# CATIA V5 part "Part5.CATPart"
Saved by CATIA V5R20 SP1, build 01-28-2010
Part number: Part3
Material "Iron": density 7870 kg/m3, Young's modulus 1.2e+11 Pa, Poisson ratio 0.291, thermal expansion 1.21e-05 1/K
Bounding box of the stored display mesh (mm): x -33.596 to 19.999, y -10 to 10, z -170 to 85.757
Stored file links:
  E:\Ehsan\My Websites\CATIA98.ir\3. Tutorials\3. Assembely Design\Assembly Design-17\Part5.CATPart
  D:\CATIA V5R20\B20\intel_a\startup\materials\Catalog.CATMaterial
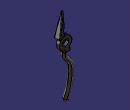
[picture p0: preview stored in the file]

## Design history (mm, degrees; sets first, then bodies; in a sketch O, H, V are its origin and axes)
Body1 (main body), material "Iron"
  Sketch1 on zx-plane, origin (0, 0, 0), H (-1, 0, 0), V (0, 0, 1)
    arc A1 centre (0, 0) radius 20 from (0, 20) to (-14.8215, 13.4284) ccw
    circle A2 centre (0, 0) radius 10
    line L1 (0, 20) -> (0, 89.7223)
    line L2 (-17.7324, 14.0566) -> (-14.8215, 13.4284)
    line L3 (0, 89.7223) -> (-1.4049, 89.7223)
    line L4 (-1.4049, 89.7223) -> (-17.7324, 14.0566)
    arc A3 centre (0, 0) radius 20 from (-14.8215, 13.4284) to (0, -20) ccw
    line L5 (0, -20) -> (0, -30)
    line L6 (13.1971, -15.0279) -> (15.7182, -20)
    arc A4 centre (0, 0) radius 20 from (0, -20) to (13.1971, -15.0279) ccw
    arc A5 centre (0, 0) radius 20 from (13.1971, -15.0279) to (0, 20) ccw
    line L7 (15.7182, -20) -> (15.7182, -30)
    line L8 (0, -30) -> (15.7182, -30)
  Pad1: profile Sketch1.L4, length 10, mirrored extent
  Sketch2 on face of Pad1 from Sketch1.L1, origin (0, 0, 0), H (0, -1, 0), V (0, 0, 1)
    line L1 (-9.6405, 20) -> (-2.0443, 89.7223)
    line L2 (10, 20) -> (2.2964, 89.7223)
    line L3 (-2.0443, 89.7223) -> (2.2964, 89.7223)
    line L4 (-9.6405, 20) -> (10, 20)
  Sketch3 on end face of Pad1, origin (0, 10, 0), H (-1, 0, 0), V (0, 0, 1)
    line L1 (0, 20) -> (-14.5611, 13.7104)
  Pocket1: profile Sketch2.L1, direction along Sketch3.L1, length 60, outer side
  Pad2: profile Sketch1.A4, length 10
  Pocket2: profile Sketch1.A2, length 10
  Pad3: profile Sketch1.L5, length 10, mirrored extent
  Plane1: type Offset, RefPlane face of Pad3 from Sketch1.L8, Offset 0, reversed
  Sketch4 on start face of Pad2, origin (0, 0, 0), H (1, 0, 0), V (0, 0, 1)
  Plane2: type Offset, RefPlane face of Pad3 from Sketch1.L8, Offset 140, reversed
  Sketch5 on start face of Pad2, origin (0, 0, 0), H (1, 0, 0), V (0, 0, 1)
    spline S1 through (-7.8799, -30) (-7.8799, -46.5682) (-15.7597, -56.9261) (-24.7786, -74.6826) (-18.86, -144.2288) (-7.0446, -170)
  Sketch6 on Plane1, origin (0, 0, -30), H (1, 0, 0), V (0, 1, 0)
    circle A1 centre (-8.0356, 0) radius 7.3015
  Sketch7 on Plane2, origin (0, 0, -170), H (1, 0, 0), V (0, 1, 0)
    circle A1 centre (-7.0446, 0) radius 7.8346
  Loft1: solid, Sections (Sketch6; Sketch7), Spine Sketch5
  Fillet1: radius 5, on edge [face of Loft1 | face of Loft1]
  Fillet2: radius 2.5, on edge [start face of Pad3 | face of Pad3 from Sketch1.L8]
  Fillet3: radius 2.5, on edge [face of Pad3 from Sketch1.L8 | face of Pad3]
  Fillet4: radius 2.5, on face of Pad3 from Sketch1.L6
  Fillet5: radius 0.5, on edge [face of Pad3 from Sketch1.L7 | face of Pad3 from Sketch1.L8]
  Fillet6: radius 2, on edge [face of Pad1 from Sketch1.L4 | face of Pocket1 from Sketch2.L2]
  Fillet7: radius 2, on edge [face of Pocket1 from Sketch2.L1 | face of Pad1 from Sketch1.L4]
  Fillet8: radius 0.5, on edge [face of Pad1 from Sketch1.L2 | face of Pad1 from Sketch1.L4]
  Fillet9: radius 1.25, on edge [face of Loft1 | face of Pad3 from Sketch1.L8]
  Fillet10: radius 1.25, on face of Pocket1 from Sketch2.L3
  Sketch8 on start face of Pad2, origin (0, 0, 0), H (1, 0, 0), V (0, 0, 1)
    line L1 (1.3092, 39.9704) -> (4.385, 39.9704)
    line L2 (4.385, 39.9704) -> (4.385, 24.4142)
    line L3 (4.385, 24.4142) -> (1.3092, 24.4142)
  Pocket3: profile Sketch8, direction (0, 1, 0), length 20, mirrored extent
  Pad4: profile Sketch1.L5, length 10, mirrored extent
Current feature: Pocket3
